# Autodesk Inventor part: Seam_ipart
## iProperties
Shininess: 69.0
Length Units: 11269
Angle Units: 11279
Time Units: 11290
Mass Units: 11283
Length Display Precision: 3
Angle Display Precision: 2
Created: 2001-05
Part Number: Seam_ipart
Material: Standard
Document SubType Name: Modellieren
Designer: dl
Density: 1 g/cm^3
Density: 0.0
Volumn: 0.0
Area: 0.0
PropertySet Name: Model Information
Control State: 0
Master: False
Checked Out: False
Author: dl
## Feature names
1. Extrusion1
2. Extrusion2
3. Mirror1
